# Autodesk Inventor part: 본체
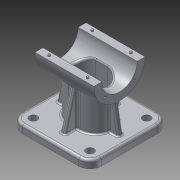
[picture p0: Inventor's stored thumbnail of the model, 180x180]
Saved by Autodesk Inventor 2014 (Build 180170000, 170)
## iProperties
Created: 2015-12
Part Number: 본체
Material: 알루미늄 6061
Document SubType Name: Modeling
Designer: mduedu
Density: 2.71 g/cm^3
Appearance: 알루미늄 - 평지
Mass: 518.779 g
Surface Area: 500.213 cm^2
Volume: 191.431 cm^3
Author: mduedu
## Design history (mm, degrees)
sketch "스케치1"
  geometry: L1 (-50, -50)-(50, -50); L2 (50, -50)-(50, 50); L3 (50, 50)-(-50, 50); L4 (-50, 50)-(-50, -50); L5 (-50, -50)-(50, 50); L6 (50, -50)-(-50, 50); 2 further points
  constraints: 12 end point, 2 midpoint, 2 parallel, 1 coincident, 1 horizontal, 1 perpendicular
  dimensions: "d154" = 100 distance of L2.end L3.end; "d155" = 100 distance of L3.end L1.start
extrude "돌출1" new body sketch "스케치1" distance "d3" = 10; taper "d4" = 0 deg
sketch "스케치2"
  geometry: C1 r 32.5 at (80, 0); 1 further point
  constraints: 1 centre point, 1 horizontal alignment
  dimensions: "d5" = 65 diameter of C1; "d125" = 80 distance of C1.centre point (0, 0)
extrude "돌출2" join sketch "스케치2" stored distance "d7" = 75; taper "d8" = 0 deg
sketch "스케치3"
  geometry: L1 (-27.5, -20)-(27.5, -20); L2 (27.5, -20)-(27.5, 20); L3 (27.5, 20)-(-27.5, 20); L4 (-27.5, 20)-(-27.5, -20); L5 (-27.5, -20)-(27.5, 20); L6 (27.5, -20)-(-27.5, 20); 1 further point
  constraints: 12 end point, 2 midpoint, 2 parallel, 1 horizontal, 1 perpendicular
  dimensions: "d9" = 55 distance of L2.end L3.end; "d11" = 40 distance of L1.end L2.end
extrude "돌출3" new body sketch "스케치3" stored distance "d12" = 75; taper "d13" = 0 deg
fillet "모깎기1"
fillet "모깎기2"
feature "결합1"
  node "솔리드2"
sketch "스케치4"
  geometry: L1 (-37.5, 47.5)-(37.5, 47.5) reference; L2 (32.5, 47.5)-(39.112, 10); L3 (37.5, 47.5)-(37.5, 112.5) reference; L4 (50, 10)-(-50, 10) reference; 1 further point
  constraints: 2 end point, 2 point on line
  dimensions: "d15" = 5 distance from line of L2.start L3; "d126" = 80 deg angle of L2 L1
feature "리브1" dims "d19" = 1, "d20" = 6, "d21" = 0, "d22" = 0, "d23" = 1, "d24" = 1
feature "리브2" dims "d25" = 1, "d26" = 6, "d27" = 0, "d28" = 0, "d29" = 1, "d30" = 1
fillet "모깎기4" dims "d31" = 2
fillet "모깎기5" dims "d32" = 2
fillet "모깎기6" dims "d33" = 2
fillet "모깎기7" dims "d41" = 14
hole "구멍2" diameter "d44" = 45; stored, may be unused: countersink angle "d48" = 90 deg, drill point angle "d50" = 118 deg; dims "d42" = 10, "d43" = 10, "d45" = 6, "d46" = 4, "d47" = 2, "d49" = 8
sketch "스케치7" dims "d52" = 26.5
  geometry: L1 (0, 0)-(32.5, 0); L2 (0, 0)-(22.981, 22.981); A1 r 32.5 centre (0, 0) between (32.5, 0) and (22.981, 22.981) reference; 3 further points
  constraints: 4 end point, 2 point on circle, 1 coincident, 1 horizontal, 1 point on line, 3 other
  dimensions: "d51" = 45 deg angle of L2 L1
hole "구멍3" sketch "스케치7" at (18.738, 18.738) diameter "d54" = 2.459; stored, may be unused: countersink angle "d58" = 90 deg, drill point angle "d60" = 118 deg; dims "d55" = 8, "d56" = 4, "d57" = 2, "d59" = 10
sketch "스케치9"
  geometry: L1 (-75, 82.5)-(75, 82.5); L2 (75, 82.5)-(75, 0); L3 (75, 0)-(-75, 0); L4 (-75, 0)-(-75, 82.5); C1 r 32.5 at (0, 0) reference; 2 further points
  constraints: 8 end point, 2 parallel, 1 coincident, 1 horizontal, 1 midpoint, 1 perpendicular
  dimensions: "d71" = 50 distance edge to line of C1 L1; "d116" = 150 distance between parallel lines of L2 L4
extrude "돌출5" cut sketch "스케치9" stored distance "d73" = 0; taper "d74" = 0 deg
node "작업 평면1"
sketch "스케치10"
  geometry: L1 (-7.5, 15)-(7.5, 15); L2 (-7.5, -15)-(7.5, -15); A1 r 20 centre (-7.5, 0) between (-7.5, 20) and (-26.977, 4.545) reference; A2 r 20 centre (7.5, 0) between (26.977, 4.545) and (7.5, 20) reference; A3 r 15 centre (-7.5, 0) between (-7.5, 15) and (-7.5, -15); A4 r 15 centre (7.5, 0) between (7.5, -15) and (7.5, 15); 1 further point
  constraints: 7 point on circle, 4 end point, 4 tangent, 3 point on line, 2 centre point, 2 coincident, 1 horizontal
  dimensions: "d77" = 5 radial gap between concentric circles of A3 A1
extrude "돌출6" cut sketch "스케치10" stored distance "d78" = 50; taper "d79" = 0 deg
fillet "모깎기10" dims "d80" = 3
sketch "스케치11"
  geometry: 2 further points
  constraints: 1 coincident
hole "구멍4" sketch "스케치11" at (0, 0) diameter "d81" = 12; stored, may be unused: countersink angle "d85" = 90 deg, drill point angle "d87" = 118 deg; dims "d82" = 8, "d83" = 40, "d84" = 10, "d86" = 10
sketch "스케치12"
  geometry: C1 r 10 at (0, 0); 1 further point
  constraints: 1 centre point, 1 coincident
  dimensions: "d88" = 20 diameter of C1
extrude "돌출7" cut sketch "스케치12" distance "d89" = 5; taper "d90" = 0 deg
chamfer "모따기1" distance "d91" = 1; stored, may be unused: second distance "d92" = 2, angle "d93" = 45 deg
fillet "모깎기11" dims "d94" = 0.5
fillet "모깎기12" dims "d115" = 0.3
sketch "스케치15"
  geometry: L1 (-75, 55)-(-75, 65) reference; L2 (0, 65)-(0, 55) reference; L3 (-75, 60)-(0, 60); C1 r 1.5 at (-62, 60); 1 further point
  constraints: 2 end point, 2 midpoint, 1 centre point, 1 point on line
  dimensions: "d117" = 3 diameter of C1; "d118" = 13 distance from line of C1.centre L1
extrude "돌출8" join sketch "스케치15" distance "d119" = 1.8; taper "d120" = 0 deg
chamfer "모따기2" distance "d121" = 0.5; stored, may be unused: second distance "d122" = 2, angle "d123" = 45 deg
sketch "스케치19"
  geometry: A1 r 14 centre (-36, -36) between (-50, -36) and (-36, -50) reference; A2 r 14 centre (-36, 36) between (-36, 50) and (-50, 36) reference; A3 r 14 centre (36, 36) between (50, 36) and (36, 50) reference; A4 r 14 centre (36, -36) between (36, -50) and (50, -36) reference; 5 further points
  constraints: 4 coincident
hole "구멍9" sketch "스케치19" at (-36, -36), (36, -36), (36, 36), (-36, 36) diameter "d156" = 10; stored, may be unused: countersink angle "d160" = 90 deg, drill point angle "d162" = 0 deg; dims "d157" = 6, "d158" = 4, "d159" = 2, "d161" = 8
node "솔리드1"
sketch "스케치5"
  geometry: L1 (10, 35)-(56.569, 22.522); L2 (10, 20)-(54.383, 20) reference; L3 (10, -50)-(10, 50) reference; A1 r 32.5 centre (80, 0) between (56.569, 22.522) and (54.383, 20) reference; 1 further point
  constraints: 2 end point, 1 point on circle, 1 point on line
  dimensions: "d128" = 15 distance of L1.start L2.start
mirror "대칭1"
mirror "대칭2"
pattern_circular "원형 패턴1" dims angle "d62" = 360 deg
mirror "대칭3"
mirror "대칭5"
mirror "대칭6"
